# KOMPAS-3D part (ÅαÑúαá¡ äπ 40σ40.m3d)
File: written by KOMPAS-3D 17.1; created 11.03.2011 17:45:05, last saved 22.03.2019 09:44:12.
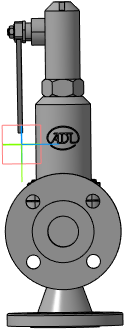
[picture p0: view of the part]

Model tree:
1. Операция без истории:1

Referenced files in C:\Users\tra\Desktop\Детали с марк. для Сферы\bsv\Desktop\Si 57\: VIC_496_25x40_3d.a3d
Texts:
  Viktor2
